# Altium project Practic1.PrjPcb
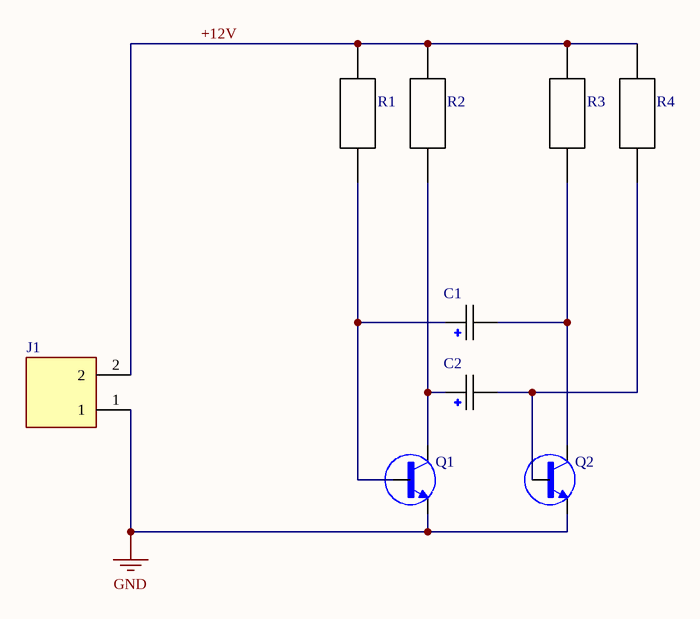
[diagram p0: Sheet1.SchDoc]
1 sheet, 9 parts. Net scope: global (net labels, ports and power ports of the same name join across sheets).
Board file: PCB1.PcbDoc

## Sheet Sheet1.SchDoc
size A4; SheetNumber: 1; SheetTotal: 1

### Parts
C1  UVR1H010MDD  [CAPPRD200W50D550H1250]  (value not drawn)
C2  UVR1H010MDD  [CAPPRD200W50D550H1250]  (value not drawn)
J1  KF301-2P  [HANDSON_KF301-2P]  (value not drawn)
Q1  2N3904  [TO92254P460H750-3]  (value not drawn)
Q2  2N3904  [TO92254P460H750-3]  (value not drawn)
R1  (no value)  [RESAD700W45L350D185]
R2  3-1623927-1  [RESAD700W45L350D185]  (value not drawn)
R3  MFR-25FBF52-10K  [RESAD1100W55L680D260]  (value not drawn)
R4  MFR-25FBF52-10K  [RESAD1100W55L680D260]  (value not drawn)

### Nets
GND: J1.1 Q1.1(E) Q2.1(E)
+12V: J1.2 R1.2 R2.2 R3.2 R4.2
NetC1_1: C1.1 Q1.2(B) R1.1
NetC1_2: C1.2 Q2.3(C) R3.1
NetC2_1: C2.1 Q1.3(C) R2.1
NetC2_2: C2.2 Q2.2(B) R4.1

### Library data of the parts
C1 C2 = UVR1H010MDD: 1 ÂµF 50 V Aluminum Electrolytic Capacitors Radial, Can - 2000 Hrs @ 85Â°C; MF: Nichicon
J1 = KF301-2P: 2 Pin Terminal Block 5mm Pitch; MF: Handson Technology
Q1 Q2 = 2N3904: BJT, TO-92, 40V, 200mA, NPN, 0.625W, 150Â°C; MF: Diotec Semiconductor
R1 R2 = 3-1623927-1: 1 MOhms Â±5% 0.25W, 1/4W Through Hole Resistor Axial - Carbon Film; MF: TE Connectivity
R3 R4 = MFR-25FBF52-10K: 10.2 kOhms Â±1% 0.25W, 1/4W Through Hole Resistor Axial - Metal Film; MF: Yageo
